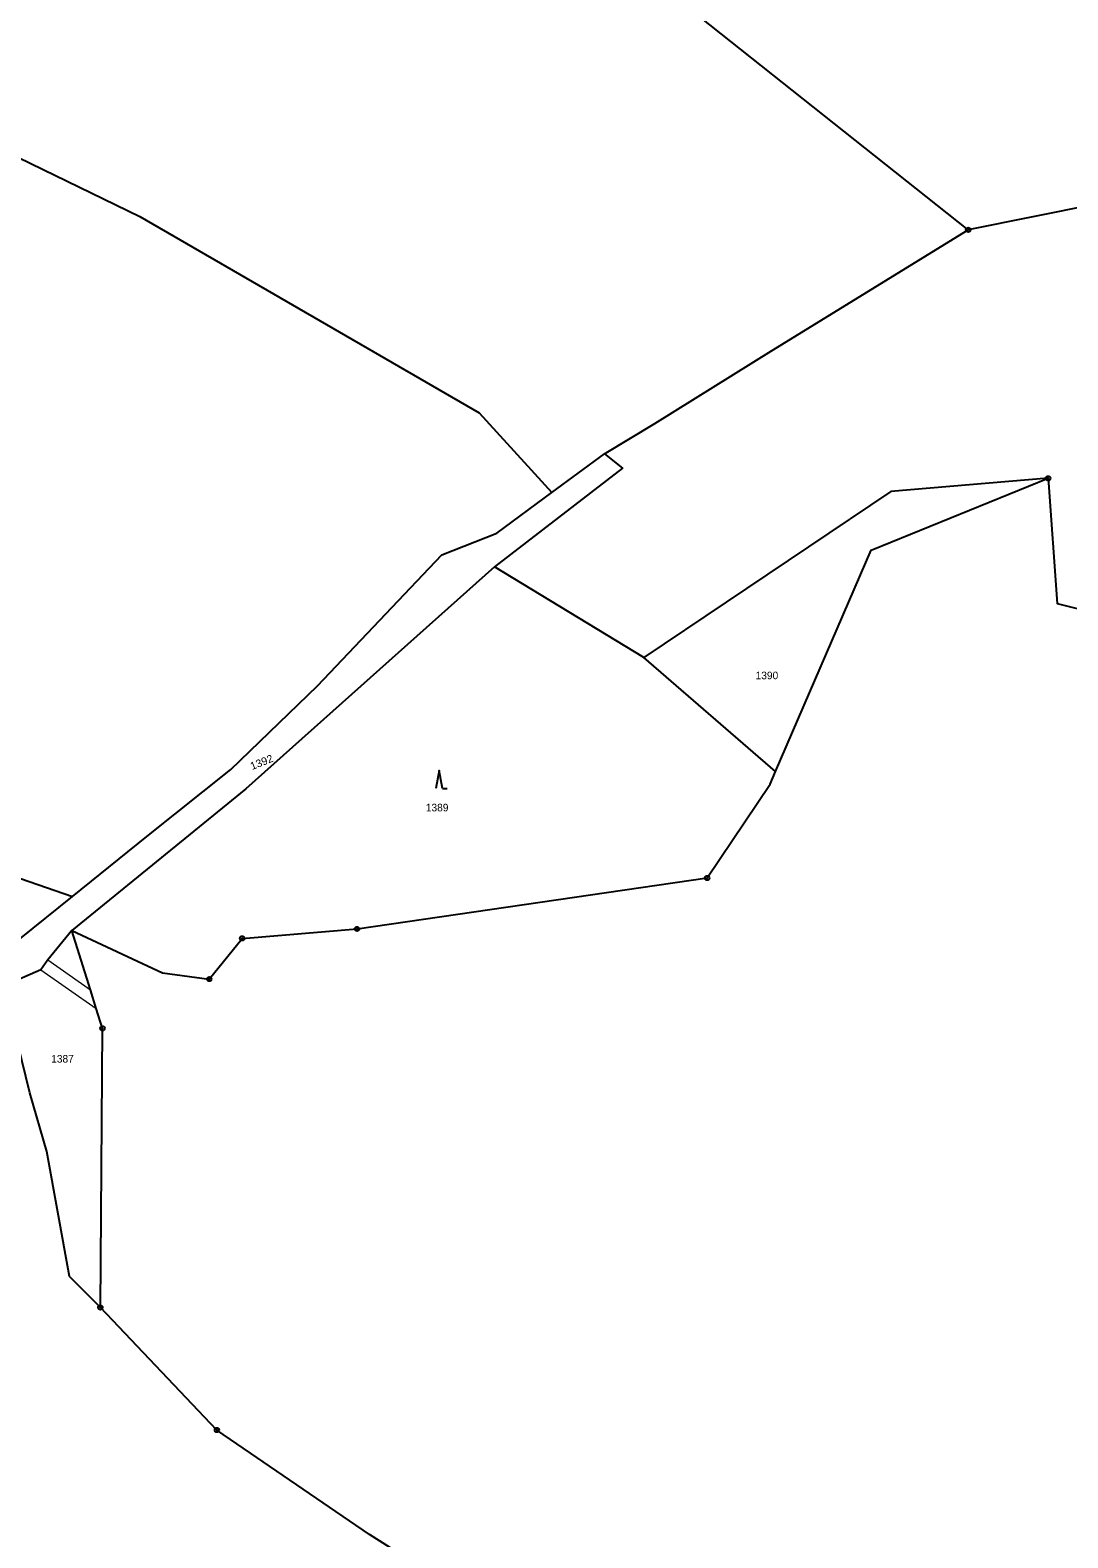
# Model space of a CAD drawing. Extents: x -872229 to -869198, y -1075981 to -1074329.
# Drawn here: x -870272.3 to -870040, y -1074936.4 to -1074598.7 of the extents above; entities that cross this region are included whole.
import ezdxf

# ---------------------------------------------------------------- set-up
doc = ezdxf.new("R2010")
doc.units = 0
doc.header["$LTSCALE"] = 0.68
for name, color, linetype, lineweight in [('1', 7, 'Continuous', 25), ('3', 7, 'Continuous', 25), ('4', 7, 'Continuous', 13), ('8', 7, 'Continuous', 25)]:
    doc.layers.add(name, color=color, linetype=linetype, lineweight=lineweight)
doc.layers.add('2', color=7, linetype='Continuous')

msp = doc.modelspace()

# ---------------------------------------------------------------- linework, layer by layer
at = {"layer": '1'}
msp.add_line((-870274.68, -1074802.33), (-870262.81, -1074792.73), dxfattribs=at)
for points in [[(-870143.77, -1074693.61), (-870132.5, -1074686.79), (-870106.37, -1074670.55), (-870062.32, -1074643.41), (-870191.72, -1074540.63)], [(-870357.04, -1074569.54), (-870334.99, -1074573.21), (-870317.65, -1074591.75), (-870314.76, -1074611.74), (-870277.71, -1074625.88), (-870247.77, -1074640.47), (-870171.77, -1074684.38), (-870155.5, -1074702.23), (-870143.77, -1074693.61)], [(-869844.44, -1074604.77), (-869905.34, -1074611.83), (-870062.32, -1074643.41)], [(-870044.43, -1074699.07), (-870042.4, -1074727.1), (-870020.9, -1074732.51), (-870004.05, -1074723.11), (-869911.02, -1074678.28)], [(-870143.77, -1074693.61), (-870139.73, -1074696.8), (-870168.33, -1074718.91)], [(-870262.81, -1074792.73), (-870246.17, -1074779.27), (-870227.38, -1074764.31), (-870207.96, -1074745.59), (-870180.13, -1074716.24), (-870167.86, -1074711.4), (-870155.5, -1074702.23)], [(-870044.43, -1074699.07), (-870079.61, -1074702.06), (-870134.93, -1074739.24)], [(-870105.49, -1074764.74), (-870084.01, -1074715.16), (-870044.43, -1074699.07)], [(-870168.33, -1074718.91), (-870224.05, -1074768.66), (-870263, -1074800.37)], [(-870263, -1074800.37), (-870242.65, -1074809.81), (-870232.21, -1074811.24), (-870224.84, -1074802.12), (-870199.14, -1074800), (-870120.77, -1074788.59), (-870106.68, -1074767.61), (-870105.49, -1074764.74), (-870134.93, -1074739.24), (-870168.33, -1074718.91)], [(-870383.96, -1074724.98), (-870370.29, -1074739.68), (-870354.63, -1074752.92), (-870327.13, -1074770.46), (-870262.81, -1074792.73)], [(-870263, -1074800.37), (-870268.38, -1074806.91), (-870269.92, -1074809.15), (-870277.75, -1074812.62), (-870281.03, -1074819.44)], [(-870256.59, -1074884.78), (-870256.11, -1074822.27), (-870257.5, -1074817.83), (-870258.82, -1074813.64), (-870263, -1074800.37)], [(-870256.59, -1074884.78), (-870263.53, -1074877.85), (-870268.59, -1074849.87), (-870272.4, -1074836.68), (-870275.99, -1074822.05), (-870281.03, -1074819.44)], [(-870115.36, -1074981.96), (-870158.79, -1074959.47), (-870196.33, -1074935.63), (-870230.5, -1074912.24), (-870256.59, -1074884.78)]]:
    msp.add_lwpolyline(points, dxfattribs=at)
at = {"layer": '3'}
msp.add_line((-870179.97, -1074768.54), (-870178.974, -1074768.54), dxfattribs=at)
msp.add_lwpolyline([(-870179.97, -1074768.54), (-870180.72, -1074764.54), (-870181.47, -1074768.54)], dxfattribs=at)
at = {"layer": '4'}
for p, q in [((-870268.38, -1074806.91), (-870258.82, -1074813.64)), ((-870269.92, -1074809.15), (-870257.5, -1074817.83))]:
    msp.add_line(p, q, dxfattribs=at)
at = {"layer": '8'}
for centre, radius in [((-870062.32, -1074643.4099), 0.5), ((-870062.32, -1074643.4099), 0.0303), ((-870044.43, -1074699.0699), 0.5), ((-870044.43, -1074699.0699), 0.0303), ((-870120.77, -1074788.5899), 0.5), ((-870120.77, -1074788.5899), 0.0303), ((-870199.14, -1074799.9999), 0.5), ((-870199.14, -1074799.9999), 0.0303), ((-870224.84, -1074802.1199), 0.5), ((-870224.84, -1074802.1199), 0.0303), ((-870232.21, -1074811.2399), 0.5), ((-870232.21, -1074811.2399), 0.0303), ((-870256.11, -1074822.2699), 0.5), ((-870256.11, -1074822.2699), 0.0303), ((-870256.59, -1074884.7799), 0.5), ((-870256.59, -1074884.7799), 0.0303), ((-870230.5, -1074912.2399), 0.5), ((-870230.5, -1074912.2399), 0.0303)]:
    msp.add_circle(centre, radius, dxfattribs=at)

# ---------------------------------------------------------------- texts
at = {"layer": '2'}
for s, p in [('1390', (-870109.91, -1074744.08)), ('1389', (-870183.73, -1074773.67)), ('1387', (-870267.59, -1074829.94))]:
    msp.add_text(s, height=1.7, dxfattribs=at).set_placement(p)
at = {"layer": '2', "width": 1.05}
msp.add_text('1392', height=1.7, rotation=22, dxfattribs=at).set_placement((-870222.631, -1074764.438))

doc.saveas('drawing.dxf')
